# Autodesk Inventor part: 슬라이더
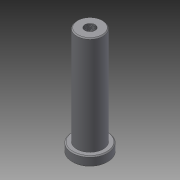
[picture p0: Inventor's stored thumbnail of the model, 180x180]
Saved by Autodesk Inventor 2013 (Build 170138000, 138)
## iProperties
Created: 2010-03
Part Number: 슬라이더
Document SubType Name: Modeling
Designer: Administrator
Density: 1 g/cm^3
Material: 강철, 연강
Mass: 73.8605 g
Surface Area: 132.046 cm^2
Volume: 73.8605 cm^3
Author: Administrator
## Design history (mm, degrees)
sketch "스케치1"
  geometry: C1 r 14 at (0, 0); 1 further point
  constraints: 1 centre point, 1 coincident
  dimensions: "d2" = 28 diameter of C1
extrude "돌출1" new body sketch "스케치1" distance "d0" = 105; taper "d1" = 0 deg
chamfer "모따기1" distance "d3" = 1; stored, may be unused: second distance "d4" = 2, angle "d5" = 45 deg
hole "구멍1" diameter "d16" = 10.917; stored, may be unused: countersink angle "d20" = 90 deg, drill point angle "d22" = 118 deg; dims "d14" = 10, "d15" = 10, "d17" = 15, "d18" = 4, "d19" = 2, "d21" = 20
sketch "스케치4"
  geometry: C1 r 19 at (0, 0); 1 further point
  constraints: 1 centre point, 1 coincident
  dimensions: "d23" = 38 diameter of C1
extrude "돌출4" join sketch "스케치4" distance "d24" = 10; taper "d25" = 0 deg
chamfer "모따기2" distance "d26" = 1; stored, may be unused: second distance "d27" = 2, angle "d28" = 45 deg
node "솔리드1"
